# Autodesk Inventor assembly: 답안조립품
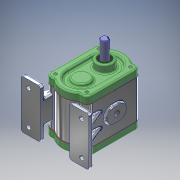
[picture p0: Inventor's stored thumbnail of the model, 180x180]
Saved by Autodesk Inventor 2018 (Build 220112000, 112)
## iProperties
Created: 2023-06
Part Number: 답안조립품
Material: 일반
Document SubType Name: Assembly
Designer: home
Author: home
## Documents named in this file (12)
- C:\Users\home\Desktop\730606V1018\답안조립품.iam
- C:\Users\home\Desktop\730606V1018\본체.ipt
- C:\Users\home\Desktop\730606V1018\뒷커버.ipt
- C:\Users\home\Desktop\730606V1018\앞커버.ipt
- C:\Users\home\Desktop\730606V1018\니들베어링 NA 4902.ipt
- C:\Users\home\Desktop\730606V1018\오일실 15 25 7.ipt
- C:\Users\home\Desktop\730606V1018\샤프트.ipt
- C:\Users\home\Desktop\730606V1018\서브 드라이브 기어.ipt
- C:\Users\home\Desktop\730606V1018\가스켓.ipt
- C:\Users\home\Desktop\730606V1018\묻힘키 6x6x40.ipt
- C:\Users\home\Desktop\730606V1018\육각 소켓 머리 볼트 M8 x 100.ipt
- C:\Users\home\Desktop\730606V1018\메인 드라이브 기어.ipt
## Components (2 placed, 1 different names)
1. 가스켓:1
2. 가스켓:2
